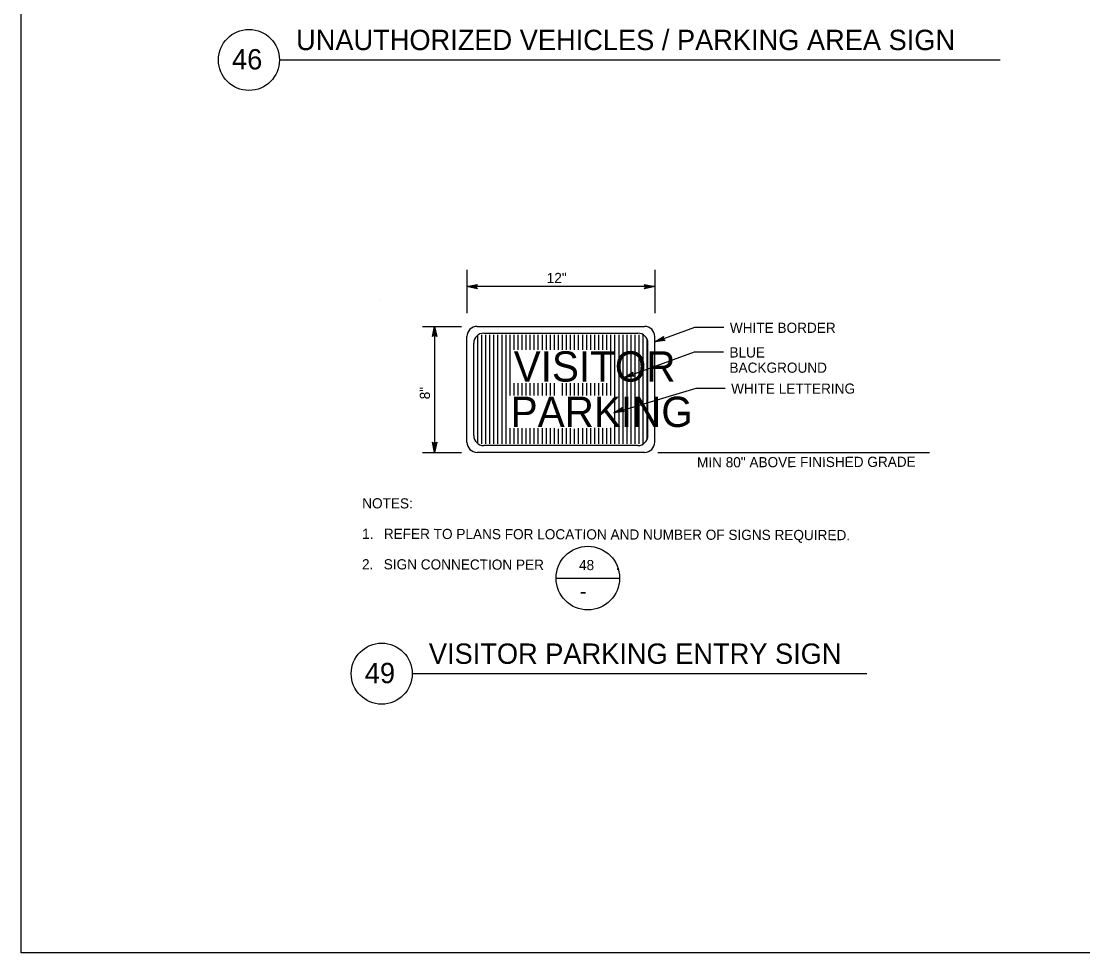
# Model space of a CAD drawing. Extents: x -121933 to -117742, y -103160 to -100084.
# Drawn here: x -119542 to -118916, y -102572 to -102023 of the extents above; entities that cross this region are included whole.
import ezdxf

# ---------------------------------------------------------------- set-up
doc = ezdxf.new("R2010")
doc.units = 0
for name, color, linetype in [('57 Undefined', 7, 'Continuous'), ('60 Nongeo Data', 7, 'Continuous'), ('Default', 7, 'Continuous'), ('G-MARK', 7, 'Continuous'), ('G-TEXT', 7, 'Continuous'), ('Misc CnstDet(22)', 7, 'Continuous'), ('Sheet Format(10)', 7, 'Continuous')]:
    doc.layers.add(name, color=color, linetype=linetype)

msp = doc.modelspace()

# ---------------------------------------------------------------- linework, layer by layer
at = {"layer": '60 Nongeo Data'}
for p, q in [((-119273.49, -102202.87), (-119174.63, -102202.87)), ((-119279.44, -102271.29), (-119279.44, -102208.78)), ((-119273.04, -102271.99), (-119273.04, -102208.08)), ((-119270.66, -102272.26), (-119270.66, -102207.81)), ((-119269.47, -102206.89), (-119178.64, -102206.89)), ((-119268.28, -102272.26), (-119268.28, -102207.81)), ((-119265.9, -102262.73), (-119265.9, -102207.81)), ((-119263.52, -102244.75), (-119263.52, -102207.81)), ((-119261.14, -102262.8), (-119261.14, -102207.81)), ((-119258.76, -102272.26), (-119258.76, -102207.81)), ((-119256.38, -102247.1), (-119256.38, -102207.81)), ((-119254, -102243.59), (-119254, -102207.81)), ((-119251.62, -102216.66), (-119251.62, -102207.81)), ((-119249.24, -102216.66), (-119249.24, -102207.81)), ((-119246.86, -102216.66), (-119246.86, -102207.81)), ((-119244.48, -102216.66), (-119244.48, -102207.81)), ((-119242.1, -102216.66), (-119242.1, -102207.81)), ((-119239.72, -102216.66), (-119239.72, -102207.81)), ((-119237.34, -102216.66), (-119237.34, -102207.81)), ((-119234.96, -102216.66), (-119234.96, -102207.81)), ((-119232.58, -102216.66), (-119232.58, -102207.81)), ((-119230.2, -102216.66), (-119230.2, -102207.81)), ((-119227.82, -102216.66), (-119227.82, -102207.81)), ((-119225.44, -102216.66), (-119225.44, -102207.81)), ((-119223.06, -102216.66), (-119223.06, -102207.81)), ((-119220.68, -102216.66), (-119220.68, -102207.81)), ((-119218.3, -102216.66), (-119218.3, -102207.81)), ((-119215.92, -102216.66), (-119215.92, -102207.81)), ((-119213.54, -102216.66), (-119213.54, -102207.81)), ((-119211.16, -102216.66), (-119211.16, -102207.81)), ((-119208.78, -102216.66), (-119208.78, -102207.81)), ((-119206.4, -102216.66), (-119206.4, -102207.81)), ((-119204.02, -102216.66), (-119204.02, -102207.81)), ((-119201.64, -102216.66), (-119201.64, -102207.81)), ((-119199.26, -102216.66), (-119199.26, -102207.81)), ((-119196.88, -102216.66), (-119196.88, -102207.81)), ((-119194.5, -102243.59), (-119194.5, -102207.81)), ((-119192.12, -102272.26), (-119192.12, -102207.85)), ((-119189.74, -102262.82), (-119189.74, -102207.81)), ((-119187.36, -102272.26), (-119187.36, -102207.81)), ((-119184.98, -102244.79), (-119184.98, -102207.81)), ((-119182.61, -102247.94), (-119182.61, -102207.81)), ((-119180.23, -102272.26), (-119180.23, -102207.81)), ((-119177.85, -102272.26), (-119177.85, -102207.81)), ((-119175.47, -102272.26), (-119175.47, -102207.81)), ((-119173.09, -102269.36), (-119173.09, -102210.72)), ((-119168.68, -102271.25), (-119168.68, -102208.82)), ((-119275.42, -102267.23), (-119275.42, -102212.84)), ((-119172.69, -102267.23), (-119172.69, -102212.84)), ((-119251.62, -102243.59), (-119251.62, -102236.36)), ((-119249.24, -102243.59), (-119249.24, -102236.36)), ((-119246.86, -102243.59), (-119246.86, -102236.36)), ((-119244.48, -102243.59), (-119244.48, -102236.36)), ((-119242.1, -102243.59), (-119242.1, -102236.36)), ((-119239.72, -102243.59), (-119239.72, -102236.36)), ((-119237.34, -102243.59), (-119237.34, -102236.36)), ((-119234.96, -102243.59), (-119234.96, -102236.36)), ((-119232.58, -102243.59), (-119232.58, -102236.36)), ((-119230.2, -102243.59), (-119230.2, -102236.36)), ((-119227.82, -102243.59), (-119227.82, -102236.36)), ((-119223.06, -102243.59), (-119223.06, -102236.36)), ((-119220.68, -102243.59), (-119220.68, -102236.36)), ((-119218.3, -102243.59), (-119218.3, -102236.36)), ((-119215.92, -102243.59), (-119215.92, -102236.36)), ((-119213.54, -102243.59), (-119213.54, -102236.36)), ((-119211.16, -102243.59), (-119211.16, -102236.36)), ((-119208.78, -102243.59), (-119208.78, -102236.36)), ((-119206.4, -102243.59), (-119206.4, -102236.36)), ((-119204.02, -102243.59), (-119204.02, -102236.36)), ((-119201.64, -102243.59), (-119201.64, -102236.36)), ((-119199.26, -102243.59), (-119199.26, -102236.36)), ((-119196.88, -102243.59), (-119196.88, -102236.36)), ((-119263.52, -102259.12), (-119263.52, -102244.75)), ((-119256.38, -102272.26), (-119256.38, -102247.1)), ((-119184.98, -102272.26), (-119184.98, -102244.79)), ((-119182.61, -102254.77), (-119182.61, -102247.94)), ((-119182.61, -102262.87), (-119182.61, -102254.77)), ((-119263.52, -102272.26), (-119263.52, -102259.12)), ((-119265.9, -102272.26), (-119265.9, -102262.73)), ((-119261.14, -102272.26), (-119261.14, -102262.8)), ((-119254, -102263.25), (-119254, -102263.01)), ((-119254, -102272.26), (-119254, -102263.25)), ((-119251.62, -102272.26), (-119251.62, -102263.01)), ((-119249.24, -102272.26), (-119249.24, -102263.01)), ((-119246.86, -102272.26), (-119246.86, -102263.01)), ((-119244.48, -102272.26), (-119244.48, -102263.11)), ((-119242.1, -102272.26), (-119242.1, -102263.01)), ((-119239.72, -102272.26), (-119239.72, -102263.01)), ((-119237.34, -102272.26), (-119237.34, -102262.87)), ((-119234.96, -102272.26), (-119234.96, -102262.87)), ((-119232.58, -102272.26), (-119232.58, -102262.87)), ((-119230.2, -102272.26), (-119230.2, -102263.01)), ((-119227.82, -102272.26), (-119227.82, -102263.01)), ((-119225.44, -102272.26), (-119225.44, -102263.36)), ((-119223.06, -102272.26), (-119223.06, -102263.01)), ((-119220.68, -102272.26), (-119220.68, -102263.01)), ((-119218.3, -102272.26), (-119218.3, -102263.01)), ((-119215.92, -102272.26), (-119215.92, -102263.29)), ((-119213.54, -102272.26), (-119213.54, -102263.01)), ((-119211.16, -102272.26), (-119211.16, -102263.01)), ((-119208.78, -102272.26), (-119208.78, -102262.87)), ((-119206.4, -102272.26), (-119206.4, -102263.01)), ((-119204.02, -102272.26), (-119204.02, -102262.78)), ((-119201.64, -102272.26), (-119201.64, -102262.78)), ((-119199.26, -102272.26), (-119199.26, -102263.01)), ((-119196.88, -102272.26), (-119196.88, -102263.01)), ((-119194.5, -102272.26), (-119194.5, -102262.82)), ((-119189.74, -102272.26), (-119189.74, -102262.82)), ((-119182.61, -102272.26), (-119182.61, -102262.87)), ((-119178.64, -102273.18), (-119269.47, -102273.18)), ((-119174.63, -102277.2), (-119273.49, -102277.2))]:
    msp.add_line(p, q, dxfattribs=at)
for centre, start, end in [((-119273.49, -102208.82), 90, 180), ((-119174.63, -102208.82), 0, 90), ((-119269.47, -102212.84), 90, 180), ((-119178.64, -102212.84), 0, 90), ((-119269.47, -102267.23), 180, 270), ((-119178.64, -102267.23), 270, 0), ((-119273.49, -102271.25), 180, 270), ((-119174.63, -102271.25), 270, 0)]:
    msp.add_arc(centre, 5.95, start, end, dxfattribs=at)
at = {"layer": 'Default'}
msp.add_lwpolyline([(-119542.38, -101122.36), (-117742.38, -101122.36), (-117742.38, -102572.36), (-119542.38, -102572.36)], close=True, dxfattribs=at)
at = {"layer": 'G-MARK'}
for p, q in [((-119168.68, -102179.46), (-119279.44, -102179.46)), ((-119298.49, -102202.87), (-119298.49, -102277.2))]:
    msp.add_line(p, q, dxfattribs=at)
for points in [[(-119168.68, -102212.08), (-119145.04, -102203.45), (-119127.85, -102203.45)], [(-119186.79, -102233.12), (-119145.3, -102217.97), (-119128.12, -102217.97)], [(-119192.73, -102253.92), (-119144.29, -102239.31), (-119127.1, -102239.31)]]:
    msp.add_lwpolyline(points, dxfattribs=at)
at = {"layer": 'G-TEXT'}
for p, q in [((-119279.44, -102179.46), (-119273.44, -102178.13)), ((-119273.44, -102180.8), (-119279.44, -102179.46)), ((-119279.44, -102179.46), (-119279.44, -102179.46)), ((-119273.65, -102180.44), (-119278.06, -102179.46)), ((-119278.04, -102179.45), (-119273.67, -102178.49)), ((-119276.67, -102179.46), (-119273.85, -102178.83)), ((-119273.89, -102180.08), (-119276.67, -102179.46)), ((-119275.29, -102179.46), (-119274.08, -102179.19)), ((-119274.06, -102179.73), (-119275.29, -102179.46)), ((-119273.44, -102178.13), (-119274.24, -102179.46)), ((-119274.24, -102179.46), (-119273.44, -102180.8)), ((-119273.44, -102178.13), (-119273.44, -102178.13)), ((-119173.88, -102179.46), (-119174.68, -102178.12)), ((-119174.68, -102178.12), (-119174.68, -102178.12)), ((-119174.68, -102178.12), (-119168.68, -102179.46)), ((-119168.68, -102179.46), (-119174.68, -102180.79)), ((-119174.68, -102180.79), (-119173.88, -102179.46)), ((-119174.46, -102178.47), (-119170.06, -102179.46)), ((-119170.07, -102179.46), (-119174.44, -102180.43)), ((-119171.44, -102179.45), (-119174.27, -102180.08)), ((-119174.23, -102178.83), (-119171.44, -102179.45)), ((-119174.05, -102179.18), (-119172.82, -102179.45)), ((-119172.82, -102179.45), (-119174.03, -102179.72)), ((-119168.68, -102179.46), (-119168.68, -102179.46)), ((-119273.44, -102180.8), (-119273.44, -102180.8)), ((-119174.68, -102180.79), (-119174.68, -102180.79)), ((-119299.83, -102208.87), (-119298.49, -102202.87)), ((-119299.47, -102208.66), (-119298.49, -102204.25)), ((-119298.49, -102202.87), (-119298.49, -102202.87)), ((-119298.49, -102202.87), (-119297.16, -102208.87)), ((-119298.48, -102204.27), (-119297.52, -102208.64)), ((-119298.49, -102208.07), (-119299.83, -102208.87)), ((-119299.83, -102208.87), (-119299.83, -102208.87)), ((-119299.11, -102208.42), (-119298.49, -102205.64)), ((-119298.76, -102208.25), (-119298.49, -102207.02)), ((-119298.49, -102205.64), (-119297.86, -102208.46)), ((-119298.49, -102207.02), (-119298.22, -102208.23)), ((-119297.16, -102208.87), (-119298.49, -102208.07)), ((-119297.16, -102208.87), (-119297.16, -102208.87)), ((-119168.68, -102212.08), (-119163.5, -102208.78)), ((-119167.37, -102211.6), (-119163.59, -102209.2)), ((-119166.08, -102211.14), (-119163.64, -102209.58)), ((-119163.25, -102210.77), (-119166.08, -102211.14)), ((-119164.78, -102210.67), (-119163.74, -102210)), ((-119163.53, -102210.5), (-119164.78, -102210.67)), ((-119163.5, -102208.78), (-119163.79, -102210.3)), ((-119163.79, -102210.3), (-119162.58, -102211.29)), ((-119163.5, -102208.78), (-119163.5, -102208.78)), ((-119162.58, -102211.29), (-119168.68, -102212.08)), ((-119168.68, -102212.08), (-119168.68, -102212.08)), ((-119162.91, -102211.03), (-119167.38, -102211.61)), ((-119162.58, -102211.29), (-119162.58, -102211.29)), ((-119186.79, -102233.12), (-119181.61, -102229.82)), ((-119180.7, -102232.32), (-119186.79, -102233.12)), ((-119186.79, -102233.12), (-119186.79, -102233.12)), ((-119181.02, -102232.06), (-119185.5, -102232.65)), ((-119185.49, -102232.64), (-119181.71, -102230.23)), ((-119184.2, -102232.18), (-119181.76, -102230.62)), ((-119181.37, -102231.81), (-119184.2, -102232.18)), ((-119182.9, -102231.7), (-119181.85, -102231.04)), ((-119181.65, -102231.54), (-119182.9, -102231.7)), ((-119181.61, -102229.82), (-119181.91, -102231.34)), ((-119181.91, -102231.34), (-119180.7, -102232.32)), ((-119181.61, -102229.82), (-119181.61, -102229.82)), ((-119180.7, -102232.32), (-119180.7, -102232.32)), ((-119192.73, -102253.92), (-119187.54, -102250.62)), ((-119186.63, -102253.13), (-119192.73, -102253.92)), ((-119192.73, -102253.92), (-119192.73, -102253.92)), ((-119186.95, -102252.87), (-119191.43, -102253.45)), ((-119191.42, -102253.44), (-119187.64, -102251.04)), ((-119190.13, -102252.98), (-119187.69, -102251.42)), ((-119187.3, -102252.61), (-119190.13, -102252.98)), ((-119188.83, -102252.51), (-119187.79, -102251.84)), ((-119187.58, -102252.34), (-119188.83, -102252.51)), ((-119187.54, -102250.62), (-119187.84, -102252.14)), ((-119187.84, -102252.14), (-119186.63, -102253.13)), ((-119187.54, -102250.62), (-119187.54, -102250.62)), ((-119186.63, -102253.13), (-119186.63, -102253.13)), ((-119298.49, -102277.2), (-119299.82, -102271.2)), ((-119299.82, -102271.2), (-119299.82, -102271.2)), ((-119299.82, -102271.2), (-119298.49, -102272)), ((-119298.49, -102275.81), (-119299.46, -102271.43)), ((-119298.48, -102274.43), (-119299.11, -102271.61)), ((-119298.48, -102273.05), (-119298.75, -102271.84)), ((-119298.49, -102272), (-119297.15, -102271.2)), ((-119297.15, -102271.2), (-119298.49, -102277.2)), ((-119297.5, -102271.41), (-119298.49, -102275.82)), ((-119297.86, -102271.65), (-119298.48, -102274.43)), ((-119298.21, -102271.82), (-119298.48, -102273.05)), ((-119297.15, -102271.2), (-119297.15, -102271.2)), ((-119298.49, -102277.2), (-119298.49, -102277.2))]:
    msp.add_line(p, q, dxfattribs=at)
at = {"layer": 'Misc CnstDet(22)'}
for p, q in [((-119390.04, -102045.73), (-118964.83, -102045.73)), ((-119279.44, -102169.53), (-119279.44, -102195.01)), ((-119168.68, -102169.53), (-119168.68, -102195.01)), ((-119331.22, -102187.12), (-119331.22, -102187.12)), ((-119305.61, -102202.87), (-119282.72, -102202.87)), ((-119305.61, -102202.87), (-119282.72, -102202.87)), ((-119305.61, -102277.2), (-119282.72, -102277.2)), ((-119166.85, -102277.2), (-119006.64, -102277.2)), ((-119311.7, -102407.73), (-119043.51, -102407.73))]:
    msp.add_line(p, q, dxfattribs=at)
for centre in [(-119408.04, -102045.73), (-119329.7, -102407.73)]:
    msp.add_circle(centre, 18, dxfattribs=at)
at = {"layer": 'Sheet Format(10)'}
msp.add_line((-119227.09, -102351.42), (-119189.39, -102351.42), dxfattribs=at)
msp.add_circle((-119208.14, -102351.37), 18.75, dxfattribs=at)

# ---------------------------------------------------------------- texts
at = {"layer": '57 Undefined'}
for s, p in [('WHITE BORDER', (-119124.33, -102206.73)), ('BLUE', (-119124.59, -102221.25)), ('BACKGROUND', (-119124.59, -102230.25)), ('WHITE LETTERING', (-119123.58, -102242.59))]:
    msp.add_text(s, height=6, dxfattribs=at).set_placement(p)
for s, rotation, p in [('MIN 80" ABOVE FINISHED GRADE', 0.16798, (-119143.73, -102286.1)), ('NOTES:  ', 359.83202, (-119341.24, -102310.22)), ('1.', 359.83202, (-119341.3, -102328.22)), ('REFER TO PLANS FOR LOCATION AND NUMBER OF SIGNS REQUIRED.', 359.83202, (-119328.49, -102328.22)), ('2.', 359.83202, (-119341.35, -102346.22)), ('SIGN CONNECTION PER                   .', 359.83202, (-119328.54, -102346.22))]:
    msp.add_text(s, height=6, rotation=rotation, dxfattribs=at).set_placement(p)
at = {"layer": '60 Nongeo Data'}
for s, p in [('VISITOR', (-119251.87, -102235.46)), ('PARKING', (-119253.63, -102262.21))]:
    msp.add_text(s, height=17.849, dxfattribs=at).set_placement(p)
at = {"layer": 'Misc CnstDet(22)'}
for s, p in [('UNAUTHORIZED VEHICLES / PARKING AREA SIGN', (-119380.24, -102039.94)), ('46', (-119418.03, -102051.35)), ('VISITOR PARKING ENTRY SIGN', (-119301.9, -102401.94)), ('49', (-119339.69, -102413.35))]:
    msp.add_text(s, height=12, dxfattribs=at).set_placement(p)
for s, rotation, p in [('12"', 0.16798, (-119232.37, -102177.34)), ('8"', 90.16798, (-119301.24, -102245.91))]:
    msp.add_text(s, height=6, rotation=rotation, dxfattribs=at).set_placement(p)
at = {"layer": 'Sheet Format(10)'}
for s, height, p in [('48', 6, (-119213.33, -102346.67)), ('-', 8.75, (-119212.85, -102363.42))]:
    msp.add_text(s, height=height, dxfattribs=at).set_placement(p)

doc.saveas('drawing.dxf')
